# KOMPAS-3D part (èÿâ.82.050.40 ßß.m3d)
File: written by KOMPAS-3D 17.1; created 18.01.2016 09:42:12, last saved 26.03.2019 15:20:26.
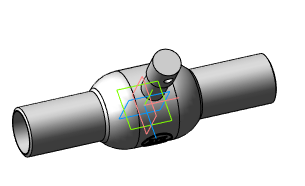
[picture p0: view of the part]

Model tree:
1. Операция без истории:5  (labels: Сталь 20  ГОСТ 1050-88)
